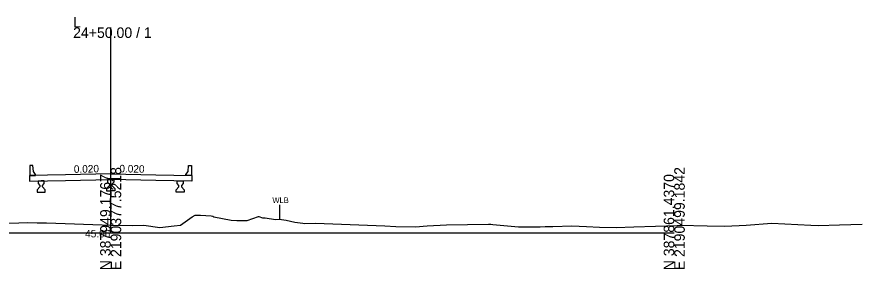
# Model space of a CAD drawing. Extents: x -26 to 2190750, y -10 to 388496.
# Drawn here: x 175 to 400, y 8490.3 to 8557.5 of the extents above; entities that cross this region are included whole.
import ezdxf

# ---------------------------------------------------------------- set-up
doc = ezdxf.new("R2010")
doc.units = 0
for name, color, linetype in [('Exist Cross Section Cell', 7, 'Continuous'), ('Exist XS Center Line Elevation Label', 7, 'Continuous'), ('Exist XS Ground Line', 7, 'Continuous'), ('Prop CMT Concrete Structures', 7, 'Continuous'), ('Prop RDY Alternate Text Blue', 7, 'Continuous'), ('Prop XS SE Text', 7, 'Continuous')]:
    doc.layers.add(name, color=color, linetype=linetype)

msp = doc.modelspace()

# ---------------------------------------------------------------- linework, layer by layer
at = {"layer": 'Exist Cross Section Cell'}
for p, q in [((200, 8500), (200, 8554.67)), ((50, 8500), (200, 8500)), ((200, 8500), (350, 8500))]:
    msp.add_line(p, q, dxfattribs=at)
at = {"layer": 'Exist XS Ground Line'}
msp.add_lwpolyline([(156.73, 8502.47), (175.52, 8502.62), (177.83, 8502.71), (180.45, 8502.61), (182.91, 8502.65), (200.19, 8502.05), (205.68, 8501.91), (208.81, 8501.97), (213.11, 8501.42), (216.87, 8501.82), (218.54, 8502.05), (221.7, 8504.27), (222.45, 8504.69), (222.96, 8504.66), (223.92, 8504.63), (226.77, 8504.48), (227.18, 8504.42), (227.42, 8504.24), (232.04, 8503.37), (233.58, 8503.24), (236.36, 8503.22), (239.3, 8504.34), (239.41, 8504.34), (240.44, 8503.98), (241.09, 8503.99), (243.85, 8503.53), (244.82, 8503.63), (246.68, 8503.35), (249.02, 8502.81), (251.16, 8502.54), (251.6, 8502.48), (254.52, 8502.58), (272.96, 8501.8), (275.91, 8501.68), (281.17, 8501.54), (284.25, 8501.79), (289.39, 8502.07), (300.58, 8502.24), (301.22, 8502.24), (301.73, 8502.22), (308.55, 8501.53), (314.31, 8501.55), (315.66, 8501.62), (317.7, 8501.66), (322.75, 8501.8), (326.67, 8501.62), (330.08, 8501.44), (334.5, 8501.42), (339.24, 8501.53), (350.74, 8501.96), (351.55, 8501.98), (358.73, 8501.87), (363.44, 8501.71), (369.17, 8502.02), (375.94, 8502.55), (386.33, 8502.04), (388.42, 8501.96), (393.98, 8502.14), (400, 8502.31)], dxfattribs=at)
at = {"layer": 'Prop CMT Concrete Structures'}
for points in [[(180, 8515.24), (180, 8515.49), (179.42, 8516.29), (179.25, 8517.87), (178.5, 8517.87), (178.5, 8515.21)], [(220, 8515.24), (220, 8515.49), (220.58, 8516.29), (220.75, 8517.87), (221.5, 8517.87), (221.5, 8515.21)], [(200, 8515.64), (188, 8515.4), (178.37, 8515.21)], [(178.37, 8515.21), (178.37, 8513.71)], [(178.5, 8515.21), (180, 8515.24)], [(200, 8514.14), (200, 8515.64)], [(200, 8515.64), (212, 8515.4), (221.62, 8515.21)], [(221.5, 8515.21), (220, 8515.24)], [(221.62, 8515.21), (221.62, 8513.71)], [(178.37, 8513.71), (188, 8513.9), (200, 8514.14)], [(182.33, 8513.78), (181.5, 8513.77), (180.67, 8513.75)], [(180.67, 8513.75), (180.67, 8513.1)], [(180.67, 8513.1), (181.17, 8512.6)], [(181.17, 8512.6), (181.17, 8512.18)], [(181.83, 8512.6), (182.33, 8513.1)], [(181.83, 8512.18), (181.83, 8512.6)], [(182.33, 8513.1), (182.33, 8513.78)], [(199.67, 8512.55), (198.92, 8511.8)], [(200, 8514.14), (199.17, 8514.12)], [(199.17, 8514.12), (199.17, 8513.47)], [(199.17, 8513.47), (199.67, 8512.97)], [(199.67, 8512.97), (199.67, 8512.55)], [(221.62, 8513.71), (212, 8513.9), (200, 8514.14)], [(200, 8514.14), (200.83, 8514.12)], [(200.83, 8513.47), (200.33, 8512.97)], [(200.33, 8512.97), (200.33, 8512.55)], [(200.33, 8512.55), (201.08, 8511.8)], [(200.83, 8514.12), (200.83, 8513.47)], [(217.67, 8513.78), (218.5, 8513.77), (219.33, 8513.75)], [(217.67, 8513.1), (217.67, 8513.78)], [(218.17, 8512.6), (217.67, 8513.1)], [(218.17, 8512.18), (218.17, 8512.6)], [(219.33, 8513.1), (218.83, 8512.6)], [(218.83, 8512.6), (218.83, 8512.18)], [(219.33, 8513.75), (219.33, 8513.1)], [(181.17, 8512.18), (180.42, 8511.43)], [(180.42, 8511.43), (180.42, 8510.77)], [(180.42, 8510.77), (181.5, 8510.77), (182.58, 8510.77)], [(182.58, 8511.43), (181.83, 8512.18)], [(182.58, 8510.77), (182.58, 8511.43)], [(198.92, 8511.8), (198.92, 8511.14)], [(198.92, 8511.14), (200, 8511.14)], [(201.08, 8511.14), (200, 8511.14)], [(201.08, 8511.8), (201.08, 8511.14)], [(217.42, 8511.43), (218.17, 8512.18)], [(217.42, 8510.77), (217.42, 8511.43)], [(219.58, 8510.77), (218.5, 8510.77), (217.42, 8510.77)], [(218.83, 8512.18), (219.58, 8511.43)], [(219.58, 8511.43), (219.58, 8510.77)]]:
    msp.add_lwpolyline(points, dxfattribs=at)
at = {"layer": 'Prop RDY Alternate Text Blue'}
msp.add_line((244.97, 8507.42), (244.97, 8503.6), dxfattribs=at)

# ---------------------------------------------------------------- texts
at = {"layer": 'Exist Cross Section Cell'}
for s, p in [('L', (190, 8554.67)), ('24+50.00 / 1', (190, 8551.87))]:
    msp.add_text(s, height=2.8, dxfattribs=at).set_placement(p)
for s, p in [('E 2190377.5218', (202.8, 8490)), ('E 2190499.1842', (352.8, 8490)), ('N 387949.1767', (200, 8490)), ('N 387861.4370', (350, 8490))]:
    msp.add_text(s, height=2.8, rotation=90, dxfattribs=at).set_placement(p)
at = {"layer": 'Exist XS Center Line Elevation Label'}
msp.add_text('45.06', height=2, dxfattribs=at).set_placement((193.2, 8498.75))
at = {"layer": 'Prop RDY Alternate Text Blue'}
msp.add_text('WLB', height=1.5, dxfattribs=at).set_placement((243.05, 8507.89))
at = {"layer": 'Prop XS SE Text'}
for rotation, p in [(1.1458, (190.21, 8515.94)), (358.8542, (202.3, 8516.09))]:
    msp.add_text('0.020', height=2, rotation=rotation, dxfattribs=at).set_placement(p)

doc.saveas('drawing.dxf')
